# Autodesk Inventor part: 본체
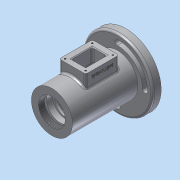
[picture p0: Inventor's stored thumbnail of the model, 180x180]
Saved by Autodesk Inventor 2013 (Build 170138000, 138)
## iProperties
Created: 2017-05
Part Number: 본체
Material: 알루미늄 6061
Document SubType Name: Modeling
Designer: dgall
Density: 2.71 g/cm^3
Mass: 719.298 g
Surface Area: 634.059 cm^2
Volume: 265.424 cm^3
Author: dgall
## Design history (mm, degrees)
sketch "스케치1"
  geometry: L1 (0, 0)-(115, 0); L2 (99, 53)-(99, 31); L3 (99, 31)-(0, 31); L4 (0, 31)-(0, 0); L5 (115, 0)-(115, 31); L6 (115, 31)-(112, 31); L7 (112, 31)-(112, 53); L8 (112, 53)-(99, 53); L9 (101, 16)-(101, 12.5); L10 (101, 12.5)-(93.7, 12.5); L11 (93.7, 12.5)-(93.7, 10); L12 (93.7, 10)-(91, 10); L13 (91, 10)-(91, 16.5); L14 (91, 16.5)-(86, 16.5); L15 (86, 16.5)-(86, 17.5); L16 (86, 17.5)-(75, 17.5); L17 (75, 17.5)-(75, 26); L18 (75, 26)-(37, 26); L19 (37, 26)-(37, 17.5); L20 (37, 17.5)-(26, 17.5); L21 (26, 17.5)-(26, 18.5); L22 (26, 18.5)-(24.25, 18.5); L23 (24.25, 18.5)-(24.25, 17.5); L24 (24.25, 17.5)-(21, 17.5); L25 (21, 17.5)-(21, 20); L26 (21, 20)-(12, 20); L27 (12, 20)-(12, 24); L28 (12, 24)-(9, 24); L29 (9, 24)-(9, 0); L30 (101, 16)-(115, 22)
  constraints: 60 end point, 20 perpendicular, 5 parallel, 2 horizontal, 2 point on line, 1 vertical
  dimensions: "d2" = 62 diameter of L3 L1; "d4" = 106 diameter of L8 L1; "d5" = 62 diameter of L6 L1; "d6" = 3 distance between parallel lines of L7 L5; "d7" = 13 distance of L7.end L2.start; "d8" = 115 distance between parallel lines of L4 L5; "d9" = 44 diameter of L30.end L1; "d10" = 32 diameter of L9.start L1; "d11" = 14 distance between parallel lines of L5 L9; "d12" = 7.3 distance of L9.end L10.end; "d13" = 2.7 distance of L11.end L12.end; "d14" = 25 diameter of L10 L1; "d15" = 20 diameter of L12 L1; "d16" = 33 diameter of L14 L1; "d17" = 5 distance between parallel lines of L15 L13; "d18" = 11 distance of L15.end L16.end; "d19" = 35 diameter of L16 L1; "d20" = 52 diameter of L18 L1; "d21" = 38 distance of L17.end L18.end; "d22" = 11 distance of L19.end L20.end; "d23" = 37 diameter of L22 L1; "d24" = 1.75 distance of L21.end L22.end; "d25" = 35 diameter of L20 L1; "d26" = 35 diameter of L24 L1; "d27" = 5 distance from line of L24.end L21; "d28" = 40 diameter of L26 L1; "d29" = 9 distance of L25.end L26.end; "d30" = 3 distance of L27.end L28.end; "d31" = 48 diameter of L28 L1
revolve "회전1" sketch "스케치1" stored, may be unused: angle "d32" = 90 deg
hole "구멍1" diameter "d35" = 40.376; stored, may be unused: countersink angle "d39" = 90 deg, drill point angle "d41" = 0 deg; dims "d33" = 10, "d34" = 10, "d36" = 9, "d37" = 4, "d38" = 2, "d40" = 9
node "작업 평면2"
  node "작업 평면1"
sketch "스케치2"
  geometry: L1 (-81, 20)-(-31, 20); L2 (-31, 20)-(-31, -20); L3 (-31, -20)-(-81, -20); L4 (-81, -20)-(-81, 20); L5 (0, 31)-(-99, 31) reference; L6 (0, 31)-(0, -31) reference; 4 further points
  constraints: 8 end point, 3 midpoint, 2 parallel, 1 horizontal, 1 horizontal alignment, 1 perpendicular, 1 vertical alignment
  dimensions: "d43" = 56 distance from line of L6 point (-56, 20); "d44" = 50 distance of L2.end L3.end; "d45" = 40 distance of L1.end L2.end
extrude "돌출1" join sketch "스케치2" stored distance "d46" = 10; taper "d47" = 0 deg
sketch "스케치3"
  geometry: L1 (31, 20)-(81, 20) reference; L2 (31, -20)-(31, 20) reference; L3 (40, 11)-(72, 11); L4 (72, 11)-(72, -11); L5 (72, -11)-(40, -11); L6 (40, -11)-(40, 11); 5 further points
  constraints: 8 end point, 4 midpoint, 2 parallel, 1 horizontal, 1 horizontal alignment, 1 perpendicular, 1 vertical alignment
  dimensions: "d48" = 32 distance of L3.start L3.end; "d50" = 22 distance of L5.end L3.start
extrude "돌출2" cut sketch "스케치3" stored distance "d51" = 10; taper "d52" = 0 deg
sketch "스케치4"
  geometry: C1 r 31 at (0, 0) reference; C2 r 53 at (0, 0) reference; A1 r 41.5 centre (0, 0) between (0, 41.5) and (41.5, 0); A2 r 4 centre (0, 41.5) between (0, 37.5) and (0, 45.5); A3 r 4 centre (41.5, 0) between (37.5, 0) and (45.5, 0); A4 r 4 centre (0, -41.5) between (0, -45.5) and (0, -37.5); A5 r 4 centre (-41.5, 0) between (-45.5, 0) and (-37.5, 0); A6 r 37.5 centre (0, 0) between (0, -37.5) and (37.5, 0); A7 r 37.5 centre (0, 0) between (0, 37.5) and (-37.5, 0); A8 r 45.5 centre (0, 0) between (0, -45.5) and (45.5, 0); A9 r 45.5 centre (0, 0) between (0, 45.5) and (-45.5, 0)
  constraints: 20 point on circle, 9 centre point, 6 vertical alignment, 3 equal radius, 2 horizontal alignment, 1 coincident
  dimensions: "d53" = 83 diameter of A1; "d54" = 8 diameter of A3
extrude "돌출3" cut sketch "스케치4" distance "d57" = 13; taper "d58" = 0 deg
sketch "스케치5"
  geometry: L1 (40, -11)-(40, 11) reference; L2 (31, 20)-(81, 20) reference; L3 (31, -20)-(31, 20) reference; L4 (35.5, 15.5)-(76.5, 15.5); L5 (76.5, 15.5)-(76.5, -15.5); L6 (76.5, -15.5)-(35.5, -15.5); L7 (35.5, -15.5)-(35.5, 15.5); 5 further points
  constraints: 8 end point, 4 midpoint, 3 horizontal alignment, 3 vertical alignment, 2 parallel, 2 perpendicular
  dimensions: "d59" = 41 distance of L4.start L4.end; "d61" = 31 distance of L4.end L5.end
hole "구멍2" sketch "스케치5" at (35.5, 15.5), (76.5, 15.5), (76.5, -15.5), (35.5, -15.5) diameter "d62" = 2.459; stored, may be unused: countersink angle "d66" = 90 deg, drill point angle "d68" = 118 deg; dims "d63" = 6, "d64" = 4, "d65" = 2, "d67" = 8
node "작업 평면3"
sketch "스케치6"
  geometry: L1 (50, -20.315)-(0, -20.315) reference; L2 (50, 0)-(50, -20.315) reference; L3 (50, 0)-(0, 0) reference; L4 (0, 0)-(0, -20.315) reference; L5 (-31, -75)-(-31, -13) reference; 2 further points
  constraints: 1 other
  dimensions: "d70" = 8 distance from line of L3 point (25, -8); "d71" = 56 distance from line of L5 point (25, -8)
feature "엠보싱1" sketch "스케치6" dims "d2" = 62, "d4" = 106, "d5" = 62, "d6" = 3, "d7" = 13, "d8" = 115, "d9" = 44, "d10" = 32, "d11" = 14, "d12" = 7.3, "d13" = 2.7, "d14" = 25, "d15" = 20, "d16" = 33, "d17" = 5, "d18" = 11, "d19" = 35, "d20" = 52, "d21" = 38, "d22" = 11, "d23" = 37, "d24" = 1.75, "d25" = 35, "d26" = 35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
fillet "모깎기1" dims "d74" = 3
fillet "모깎기2" dims "d75" = 3
fillet "모깎기3" dims "d76" = 3
chamfer "모따기1" distance "d77" = 1; stored, may be unused: second distance "d78" = 2, angle "d79" = 45 deg
fillet "모깎기4" dims "d80" = 3
chamfer "모따기2" distance "d81" = 0.7; stored, may be unused: second distance "d82" = 2, angle "d83" = 30 deg
fillet "모깎기5" dims "d84" = 3
fillet "모깎기6" dims "d85" = 0.3
fillet "모깎기7" dims "d86" = 0.3
fillet "모깎기8" dims "d87" = 3
chamfer "모따기3" distance "d88" = 1; stored, may be unused: second distance "d89" = 2, angle "d90" = 30 deg
fillet "모깎기9" dims "d91" = 3
fillet "모깎기10" dims "d92" = 3
chamfer "모따기4" distance "d93" = 1; stored, may be unused: second distance "d94" = 2, angle "d95" = 30 deg
node "솔리드1"
node "투영된 루프1"
other parameters: "d42" = 44, "d55" = 75, "d56" = 91
